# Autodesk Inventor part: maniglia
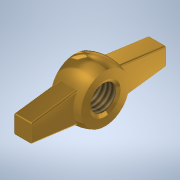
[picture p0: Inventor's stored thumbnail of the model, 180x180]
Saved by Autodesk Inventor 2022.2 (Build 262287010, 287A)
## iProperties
Created: 2014-01
Part Number: maniglia
Document SubType Name: Modeling
Designer: UTENTE
Density: 8.47 g/cm^3
Material: Ottone, Giallo chiaro
Appearance: Ottone - Satinato
Author: UTENTE
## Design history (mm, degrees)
sketch "Schizzo1"
  geometry: L1 (0, 0)-(5, 0); L2 (5, 0)-(5, 8); L3 (-5, 0)-(0, 0); L4 (-5, 0)-(-5, 8); A1 r 13 centre (0, -4) between (5, 8) and (0, 9); A2 r 13 centre (0, -4) between (0, 9) and (-5, 8)
  constraints: 8 end point, 4 point on circle, 2 centre point, 1 collinear, 1 horizontal, 1 perpendicular
revolve "Rivoluzione1" sketch "Schizzo1" stored, may be unused: angle "d4" = 90 deg
sketch "Schizzo2"
  geometry: C1 r 8 at (0, 0) reference; C2 r 8 at (0, 0) reference
  node "Proietta spigoli di taglio1"
sketch "Schizzo3"
  geometry: L1 (-22.5, 0)-(-22.5, -3); L2 (-22.5, -3)-(-4.998, -5.331); L3 (0, 0)-(0, -5.755); L4 (-22.5, 3)-(-4.998, 5.331); L5 (-22.5, 0)-(-22.5, 3); L6 (22.5, -3)-(4.998, -5.331); L7 (22.5, 0)-(22.5, -3); L8 (22.5, 0)-(22.5, 3); L9 (22.5, 3)-(4.998, 5.331); C1 r 9 at (0, 0) reference; A1 r 7.307 centre (0, 0) between (4.998, -5.331) and (4.998, 5.331); A2 r 7.307 centre (0, 0) between (-4.998, 5.331) and (-4.998, -5.331); 1 further point
  constraints: 18 end point, 4 point on circle, 2 centre point, 1 coincident
extrude "Estrusione1" join sketch "Schizzo3" stored distance "d8" = 6; taper "d9" = 0 deg
fillet "Raccordo1" dims "d10" = 0.5
sketch "Schizzo4"
  geometry: C1 r 8 at (0, 0) reference
hole "Hole1" diameter "d13" = 8.376; stored, may be unused: countersink angle "d17" = 90 deg, drill point angle "d19" = 118 deg; dims "d11" = 10, "d12" = 10, "d14" = 6, "d15" = 4, "d16" = 2, "d18" = 8
chamfer "Smusso1" distance "d20" = 1; stored, may be unused: second distance "d21" = 2, angle "d22" = 30 deg
chamfer "Smusso2" distance "d23" = 1; stored, may be unused: second distance "d24" = 2, angle "d25" = 30 deg
node "Solido1"
node "Proietta spigoli di taglio2"
